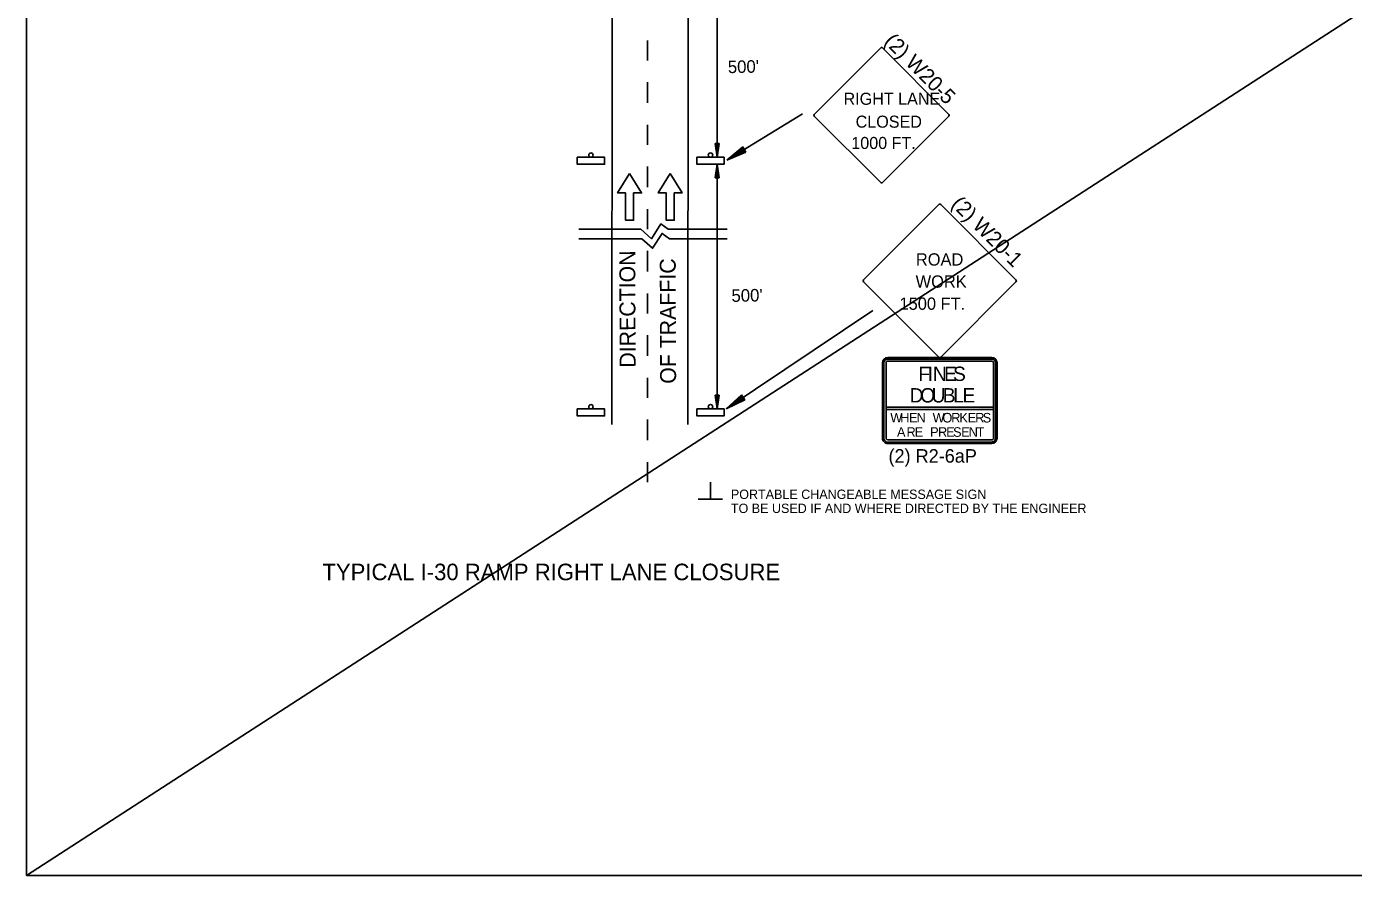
# Model space of a CAD drawing. Extents: x 1374027 to 1374537, y 380415 to 381405.
# Drawn here: x 1374367.1 to 1374452.1, y 381075.2 to 381129.5 of the extents above; entities that cross this region are included whole.
import ezdxf

# ---------------------------------------------------------------- set-up
doc = ezdxf.new("R2010")
doc.units = 0
for name, color, linetype in [('Default', 7, 'Continuous'), ('DSN_DRFT_Junk-No-Plot', 7, 'Continuous'), ('R_Exist Surface', 7, 'Continuous')]:
    doc.layers.add(name, color=color, linetype=linetype)

msp = doc.modelspace()

# ---------------------------------------------------------------- linework, layer by layer
at = {"layer": 'Default'}
for p, q in [((1374410.897, 381099.294), (1374410.897, 381100.362)), ((1374411.675, 381099.271), (1374410.111, 381099.271))]:
    msp.add_line(p, q, dxfattribs=at)
at = {"layer": 'DSN_DRFT_Junk-No-Plot'}
msp.add_line((1374367.083, 381075.174), (1374537.083, 381185.174), dxfattribs=at)
for points in [[(1374367.083, 381185.174), (1374537.083, 381185.174), (1374537.083, 381075.174), (1374367.083, 381075.174)], [(1374367.083, 381185.174), (1374367.083, 381075.174), (1374537.083, 381075.174), (1374537.083, 381185.174)]]:
    msp.add_lwpolyline(points, close=True, dxfattribs=at)
at = {"layer": 'R_Exist Surface'}
for p, q in [((1374404.621, 381173.131), (1374404.581, 381104.045)), ((1374409.48, 381173.131), (1374409.44, 381104.042)), ((1374411.326, 381121.157), (1374411.326, 381133.687)), ((1374417.542, 381123.901), (1374421.799, 381128.159)), ((1374421.909, 381128.159), (1374426.166, 381123.901)), ((1374416.8, 381123.938), (1374411.941, 381120.968)), ((1374421.799, 381119.534), (1374417.542, 381123.792)), ((1374426.166, 381123.792), (1374421.909, 381119.534)), ((1374411.195, 381122.031), (1374411.326, 381121.157)), ((1374411.195, 381122.031), (1374411.457, 381122.031)), ((1374411.217, 381122.031), (1374411.326, 381121.303)), ((1374411.239, 381122.031), (1374411.326, 381121.453)), ((1374411.261, 381122.031), (1374411.326, 381121.599)), ((1374411.284, 381122.031), (1374411.326, 381121.747)), ((1374411.306, 381122.031), (1374411.326, 381121.893)), ((1374411.457, 381122.031), (1374411.326, 381121.157)), ((1374411.369, 381122.031), (1374411.326, 381121.747)), ((1374411.413, 381122.031), (1374411.326, 381121.453)), ((1374411.435, 381122.031), (1374411.326, 381121.303)), ((1374411.391, 381122.031), (1374411.326, 381121.599)), ((1374411.347, 381122.031), (1374411.326, 381121.893)), ((1374412.957, 381121.82), (1374411.941, 381120.968)), ((1374413.162, 381121.484), (1374411.941, 381120.968)), ((1374412.974, 381121.792), (1374412.128, 381121.082)), ((1374413.145, 381121.512), (1374412.128, 381121.082)), ((1374412.992, 381121.763), (1374412.32, 381121.2)), ((1374413.128, 381121.541), (1374412.32, 381121.2)), ((1374413.009, 381121.735), (1374412.507, 381121.314)), ((1374413.111, 381121.569), (1374412.507, 381121.314)), ((1374413.026, 381121.707), (1374412.696, 381121.43)), ((1374413.093, 381121.598), (1374412.696, 381121.43)), ((1374413.044, 381121.678), (1374412.883, 381121.544)), ((1374413.076, 381121.626), (1374412.883, 381121.544)), ((1374413.162, 381121.484), (1374412.957, 381121.82)), ((1374411.195, 381119.834), (1374411.326, 381120.708)), ((1374411.217, 381119.834), (1374411.326, 381120.562)), ((1374411.326, 381105.046), (1374411.326, 381120.708)), ((1374411.457, 381119.834), (1374411.326, 381120.708)), ((1374411.435, 381119.834), (1374411.326, 381120.562)), ((1374411.457, 381119.834), (1374411.195, 381119.834)), ((1374411.239, 381119.834), (1374411.326, 381120.412)), ((1374411.261, 381119.834), (1374411.326, 381120.267)), ((1374411.283, 381119.834), (1374411.326, 381120.118)), ((1374411.306, 381119.834), (1374411.326, 381119.972)), ((1374411.413, 381119.834), (1374411.326, 381120.412)), ((1374411.391, 381119.834), (1374411.326, 381120.267)), ((1374411.369, 381119.834), (1374411.326, 381120.118)), ((1374411.347, 381119.834), (1374411.326, 381119.972)), ((1374420.7, 381113.306), (1374425.52, 381118.126)), ((1374425.644, 381118.126), (1374430.464, 381113.306)), ((1374425.52, 381108.362), (1374420.7, 381113.182)), ((1374430.464, 381113.182), (1374425.644, 381108.362)), ((1374421.285, 381111.339), (1374411.907, 381105.056)), ((1374421.91, 381107.992), (1374421.91, 381103.172)), ((1374422.006, 381107.992), (1374422.006, 381103.172)), ((1374422.139, 381103.172), (1374422.139, 381107.992)), ((1374428.91, 381108.336), (1374422.254, 381108.336)), ((1374428.91, 381108.24), (1374422.254, 381108.24)), ((1374422.254, 381108.107), (1374428.91, 381108.107)), ((1374429.024, 381107.992), (1374429.024, 381103.172)), ((1374429.158, 381103.172), (1374429.158, 381107.992)), ((1374429.254, 381103.172), (1374429.254, 381107.992)), ((1374411.195, 381105.92), (1374411.326, 381105.046)), ((1374411.195, 381105.92), (1374411.457, 381105.92)), ((1374411.217, 381105.92), (1374411.326, 381105.192)), ((1374411.239, 381105.92), (1374411.326, 381105.342)), ((1374411.261, 381105.92), (1374411.326, 381105.488)), ((1374411.284, 381105.92), (1374411.326, 381105.636)), ((1374411.306, 381105.92), (1374411.326, 381105.782)), ((1374411.457, 381105.92), (1374411.326, 381105.046)), ((1374411.369, 381105.92), (1374411.326, 381105.636)), ((1374411.413, 381105.92), (1374411.326, 381105.342)), ((1374411.435, 381105.92), (1374411.326, 381105.192)), ((1374411.391, 381105.92), (1374411.326, 381105.488)), ((1374411.347, 381105.92), (1374411.326, 381105.782)), ((1374412.887, 381105.95), (1374411.907, 381105.056)), ((1374413.106, 381105.623), (1374411.907, 381105.056)), ((1374412.906, 381105.923), (1374412.089, 381105.178)), ((1374413.088, 381105.65), (1374412.089, 381105.178)), ((1374412.924, 381105.895), (1374412.277, 381105.304)), ((1374413.07, 381105.678), (1374412.277, 381105.304)), ((1374412.943, 381105.868), (1374412.458, 381105.425)), ((1374413.051, 381105.705), (1374412.458, 381105.425)), ((1374412.961, 381105.84), (1374412.643, 381105.549)), ((1374413.032, 381105.734), (1374412.643, 381105.549)), ((1374412.98, 381105.812), (1374412.825, 381105.671)), ((1374413.014, 381105.761), (1374412.825, 381105.671)), ((1374413.106, 381105.623), (1374412.887, 381105.95)), ((1374422.139, 381105.018), (1374422.139, 381105.152)), ((1374422.139, 381105.152), (1374429.024, 381105.152)), ((1374429.024, 381105.152), (1374429.024, 381105.018)), ((1374429.024, 381105.018), (1374422.139, 381105.018)), ((1374428.91, 381103.058), (1374422.254, 381103.058)), ((1374422.254, 381102.924), (1374428.91, 381102.924)), ((1374422.254, 381102.828), (1374428.91, 381102.828))]:
    msp.add_line(p, q, dxfattribs=at)
for points in [[(1374406.867, 381128.629), (1374406.866, 381127.346)], [(1374406.865, 381125.963), (1374406.864, 381124.647)], [(1374406.863, 381123.229), (1374406.863, 381121.947)], [(1374406.862, 381120.564), (1374406.861, 381119.248)], [(1374406.86, 381117.83), (1374406.86, 381116.548)], [(1374402.458, 381116.551), (1374406.44, 381116.551), (1374407.115, 381115.944), (1374407.722, 381116.889), (1374408.195, 381116.551), (1374411.974, 381116.551)], [(1374402.458, 381115.944), (1374406.508, 381115.944), (1374407.182, 381115.336), (1374407.79, 381116.281), (1374408.262, 381115.944), (1374411.974, 381115.944)], [(1374406.859, 381115.164), (1374406.858, 381113.849)], [(1374406.858, 381112.431), (1374406.857, 381111.149)], [(1374406.856, 381109.765), (1374406.855, 381108.449)], [(1374406.855, 381107.032), (1374406.854, 381105.749)], [(1374406.853, 381104.366), (1374406.852, 381103.05)], [(1374406.851, 381101.633), (1374406.851, 381100.35)]]:
    msp.add_lwpolyline(points, dxfattribs=at)
for points in [[(1374402.366, 381121.157), (1374404.114, 381121.157), (1374404.114, 381120.708), (1374402.366, 381120.708)], [(1374410.023, 381121.157), (1374411.771, 381121.157), (1374411.771, 381120.708), (1374410.023, 381120.708)], [(1374405.713, 381120.12), (1374406.478, 381118.874), (1374405.968, 381118.874), (1374405.968, 381117.125), (1374405.458, 381117.125), (1374405.458, 381118.874), (1374404.948, 381118.874)], [(1374408.315, 381120.12), (1374409.08, 381118.874), (1374408.57, 381118.874), (1374408.57, 381117.125), (1374408.06, 381117.125), (1374408.06, 381118.874), (1374407.55, 381118.874)], [(1374402.366, 381105.046), (1374404.114, 381105.046), (1374404.114, 381104.598), (1374402.366, 381104.598)], [(1374410.023, 381105.046), (1374411.771, 381105.046), (1374411.771, 381104.598), (1374410.023, 381104.598)]]:
    msp.add_lwpolyline(points, close=True, dxfattribs=at)
for centre, radius, start, end in [((1374422.254, 381107.992), 0.344, 90, 180), ((1374422.254, 381107.992), 0.249, 90, 180.00001), ((1374422.254, 381107.992), 0.115, 90, 180.00001), ((1374428.91, 381107.992), 0.344, 0, 90), ((1374428.91, 381107.992), 0.249, 0, 90), ((1374428.91, 381107.992), 0.115, 0, 90), ((1374422.254, 381103.172), 0.344, 180, 270.00001), ((1374422.254, 381103.172), 0.249, 180.00001, 270), ((1374422.254, 381103.172), 0.115, 180.00001, 270), ((1374428.91, 381103.172), 0.344, 270.00001, 0.00001), ((1374428.91, 381103.172), 0.249, 270, 0.00001), ((1374428.91, 381103.172), 0.115, 270, 0.00001)]:
    msp.add_arc(centre, radius, start, end, dxfattribs=at)
for centre, major_axis, start_param, end_param in [((1374421.854, 381128.105), (0, -0.0772), 2.356194, 3.926991), ((1374417.596, 381123.847), (0, -0.0772), 3.926991, 5.497786), ((1374426.111, 381123.847), (0, 0.0772), 3.926992, 5.497787), ((1374421.854, 381119.589), (0, -0.0772), 5.497786, 7.068585), ((1374425.582, 381118.064), (0, -0.0874), 2.356194, 3.926991), ((1374420.762, 381113.244), (0, -0.0874), 3.926991, 5.497786), ((1374430.402, 381113.244), (0, 0.0874), 3.926992, 5.497787), ((1374425.582, 381108.423), (0, -0.0874), 5.497786, 7.068585)]:
    msp.add_ellipse(centre, major_axis=major_axis, ratio=0.999914, start_param=start_param, end_param=end_param, dxfattribs=at)
for centre in [(1374403.238, 381121.298), (1374410.895, 381121.298), (1374403.238, 381105.187), (1374410.895, 381105.187)]:
    msp.add_ellipse(centre, major_axis=(0, 0.141), ratio=0.999914, dxfattribs=at)

# ---------------------------------------------------------------- texts
at = {"layer": 'Default'}
for s, height, p in [('PORTABLE CHANGEABLE MESSAGE SIGN', 0.59997, (1374412.203, 381099.279)), ('TO BE USED IF AND WHERE DIRECTED BY THE ENGINEER', 0.59997, (1374412.203, 381098.38)), ('TYPICAL I-30 RAMP RIGHT LANE CLOSURE', 1.05792, (1374386.037, 381094.078))]:
    msp.add_text(s, height=height, dxfattribs=at).set_placement(p)
at = {"layer": 'R_Exist Surface'}
for s, height, rotation, p in [('(2) W20-5', 0.9617, 314.99755, (1374421.968, 381128.512)), ("500'", 0.8015, 1.00009, (1374412.013, 381126.543)), ('(2) W20-1', 0.9617, 314.99755, (1374426.264, 381118.092)), ('DIRECTION', 1.02, 90.19694, (1374406.1, 381107.692)), ('OF TRAFFIC', 1.02, 90.19694, (1374408.692, 381106.656)), ("500'", 0.8015, 1.00009, (1374412.246, 381111.898))]:
    msp.add_text(s, height=height, rotation=rotation, dxfattribs=at).set_placement(p)
for s, height, p in [('RIGHT LANE', 0.772, (1374419.418, 381124.518)), ('CLOSED', 0.772, (1374420.194, 381123.051)), ('1000 FT.', 0.772, (1374419.916, 381121.687)), ('ROAD', 0.7866, (1374424.053, 381114.222)), ('WORK', 0.7866, (1374424.038, 381112.807)), ('1500 FT.', 0.7866, (1374423.004, 381111.392)), ('F', 0.918, (1374424.214, 381106.835)), ('I', 0.918, (1374424.811, 381106.835)), ('N', 0.918, (1374425.141, 381106.835)), ('E', 0.918, (1374425.857, 381106.835)), ('S', 0.918, (1374426.436, 381106.835)), ('D', 0.918, (1374423.654, 381105.458)), ('O', 0.918, (1374424.333, 381105.458)), ('U', 0.918, (1374425.059, 381105.458)), ('B', 0.918, (1374425.775, 381105.458)), ('L', 0.918, (1374426.445, 381105.458)), ('E', 0.918, (1374427.041, 381105.458)), ('W', 0.612, (1374422.415, 381104.176)), ('H', 0.612, (1374423.051, 381104.176)), ('E', 0.612, (1374423.614, 381104.176)), ('N', 0.612, (1374424.098, 381104.176)), ('W', 0.612, (1374425.126, 381104.176)), ('O', 0.612, (1374425.75, 381104.176)), ('R', 0.612, (1374426.319, 381104.176)), ('K', 0.612, (1374426.84, 381104.176)), ('E', 0.612, (1374427.372, 381104.176)), ('R', 0.612, (1374427.855, 381104.176)), ('S', 0.612, (1374428.333, 381104.176)), ('A', 0.612, (1374422.84, 381103.259)), ('R', 0.612, (1374423.452, 381103.259)), ('E', 0.612, (1374423.972, 381103.259)), ('P', 0.612, (1374424.964, 381103.259)), ('R', 0.612, (1374425.472, 381103.259)), ('E', 0.612, (1374425.992, 381103.259)), ('S', 0.612, (1374426.433, 381103.259)), ('E', 0.612, (1374426.953, 381103.259)), ('N', 0.612, (1374427.436, 381103.259)), ('T', 0.612, (1374427.944, 381103.259)), ('(2) R2-6aP', 0.8655, (1374422.3, 381101.603))]:
    msp.add_text(s, height=height, dxfattribs=at).set_placement(p)

doc.saveas('drawing.dxf')
